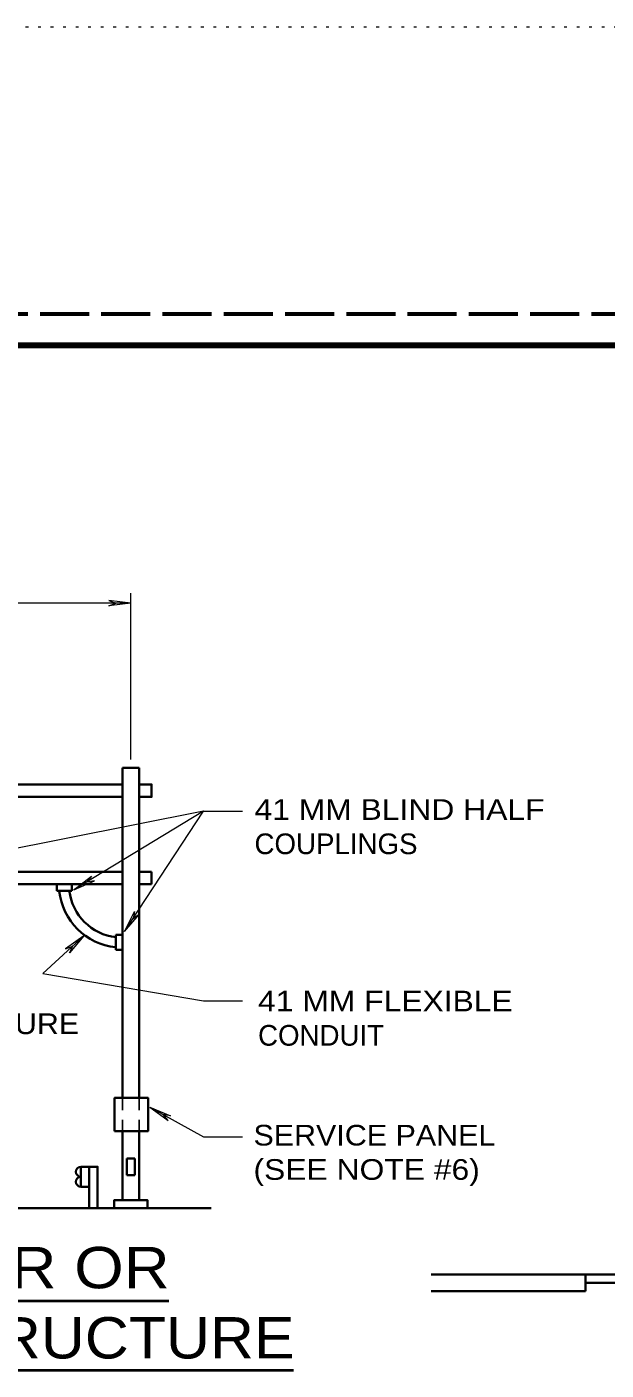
# Model space of a CAD drawing. Extents: x 312583 to 312854, y 144419 to 144597.
# Drawn here: x 312799.97 to 312821.24, y 144547.42 to 144596.78 of the extents above; entities that cross this region are included whole.
import ezdxf
from ezdxf.enums import TextEntityAlignment as Align

# ---------------------------------------------------------------- set-up
doc = ezdxf.new("R2010")
doc.units = 0
doc.header["$LTSCALE"] = 0.3
for name, pattern in [('DOTTED', [1.5, 0.3, -1.2]), ('LONG_DASHED', [7.5, 6, -1.5]), ('SHORT_DASHED', [2.7, 1.5, -1.2])]:
    doc.linetypes.add(name, pattern=pattern)
doc.layers.add('1', color=7, linetype='Continuous', lineweight=13)
doc.layers.add('63', color=7, linetype='DOTTED', lineweight=13)

msp = doc.modelspace()

# ---------------------------------------------------------------- linework, layer by layer
at = {"layer": '1', "linetype": 'LONG_DASHED', "lineweight": 60}
msp.add_line((312851.75, 144586.2246), (312583.526, 144586.2246), dxfattribs=at)
at = {"layer": '1', "lineweight": 158}
msp.add_line((312616.5, 144585.0846), (312849, 144585.0846), dxfattribs=at)
at = {"layer": '1'}
for p, q in [((312803.7798, 144575.6109), (312782.7042, 144575.6109)), ((312802.9748, 144575.7105), (312803.2278, 144575.6109)), ((312803.7798, 144575.6109), (312802.9748, 144575.7105)), ((312802.9748, 144575.5112), (312803.2278, 144575.6109)), ((312803.7798, 144575.6109), (312802.9748, 144575.5112)), ((312803.7798, 144569.8609), (312803.7798, 144575.9712)), ((312806.4478, 144567.9595), (312791.1528, 144564.9235)), ((312806.4478, 144567.9595), (312807.8892, 144567.9595)), ((312801.6945, 144565.0692), (312802.3385, 144565.5752)), ((312801.6945, 144565.0692), (312802.4458, 144565.3989)), ((312802.3385, 144565.5752), (312802.1698, 144565.3529)), ((312802.4458, 144565.3989), (312802.1698, 144565.3529)), ((312803.5575, 144563.5435), (312803.9178, 144564.2795)), ((312803.5575, 144563.5435), (312804.0865, 144564.1722)), ((312803.9178, 144564.2795), (312803.8642, 144564.0112)), ((312804.0865, 144564.1722), (312803.8642, 144564.0112)), ((312802.0548, 144563.3825), (312801.3878, 144562.9072)), ((312802.0548, 144563.3825), (312801.5258, 144562.7615)), ((312801.3878, 144562.9072), (312801.6485, 144563.0069)), ((312801.5258, 144562.7615), (312801.6485, 144563.0069)), ((312806.4478, 144560.9905), (312807.8892, 144560.9905)), ((312804.4852, 144557.0805), (312806.4478, 144555.9995)), ((312804.4852, 144557.0805), (312805.1522, 144556.5975)), ((312804.4852, 144557.0805), (312805.2442, 144556.7739)), ((312805.1522, 144556.5975), (312804.9758, 144556.8122)), ((312805.2442, 144556.7739), (312804.9758, 144556.8122)), ((312806.4478, 144555.9995), (312807.8892, 144555.9995))]:
    msp.add_line(p, q, dxfattribs=at)
at = {"layer": '1', "lineweight": 35}
for p, q in [((312804.0865, 144569.5542), (312803.4808, 144569.5542)), ((312803.4808, 144557.4255), (312803.4808, 144569.5542)), ((312804.0865, 144557.4255), (312804.0865, 144569.5542)), ((312803.4808, 144568.9485), (312791.8735, 144568.9485)), ((312803.4808, 144568.4885), (312791.8735, 144568.4885)), ((312803.4808, 144565.7362), (312791.8735, 144565.7362)), ((312804.0865, 144565.7362), (312804.5465, 144565.7362)), ((312804.5465, 144565.7362), (312804.5465, 144565.2839)), ((312803.4808, 144565.2839), (312791.8735, 144565.2839)), ((312801.0658, 144565.0385), (312801.0658, 144565.2839)), ((312801.6178, 144565.0385), (312801.6178, 144565.2839)), ((312804.0865, 144565.2839), (312804.5465, 144565.2839)), ((312801.6178, 144565.0385), (312801.0658, 144565.0385)), ((312803.2355, 144562.8689), (312803.2355, 144563.4209)), ((312803.2355, 144563.4209), (312803.4808, 144563.4209)), ((312803.2355, 144562.8689), (312803.4808, 144562.8689)), ((312803.4808, 144553.6689), (312803.4808, 144556.2065)), ((312804.0865, 144553.6689), (312804.0865, 144556.2065)), ((312801.9475, 144554.8955), (312801.9475, 144554.1595)), ((312802.2542, 144554.8955), (312802.2542, 144553.3699)), ((312803.6342, 144555.2022), (312803.9332, 144555.2022)), ((312803.6342, 144554.5889), (312803.6342, 144555.2022)), ((312803.9332, 144554.5889), (312803.9332, 144555.2022)), ((312803.6342, 144554.5889), (312803.9332, 144554.5889)), ((312802.2542, 144554.1595), (312801.9475, 144554.1595)), ((312798.2828, 144553.3699), (312806.7315, 144553.3699)), ((312820.4766, 144550.9337), (312814.811, 144550.9337)), ((312820.4766, 144550.9337), (312820.4766, 144550.3203)), ((312820.4766, 144550.3203), (312814.811, 144550.3203))]:
    msp.add_line(p, q, dxfattribs=at)
at = {"layer": '1', "linetype": 'SHORT_DASHED', "lineweight": 25}
for p, q in [((312803.4808, 144557.4255), (312803.4808, 144556.2065)), ((312804.0865, 144557.4255), (312804.0865, 144556.2065))]:
    msp.add_line(p, q, dxfattribs=at)
at = {"layer": '1', "lineweight": 40}
for p, q in [((312776.2125, 144549.9677), (312805.1771, 144549.9677)), ((312770.6431, 144547.4229), (312809.7605, 144547.4229))]:
    msp.add_line(p, q, dxfattribs=at)
at = {"layer": '1', "lineweight": 35}
for points in [[(312804.0865, 144568.9485), (312804.5465, 144568.9485), (312804.5465, 144568.4885), (312804.0865, 144568.4885)], [(312802.5608, 144553.3699), (312802.5608, 144554.8955), (312801.9475, 144554.8955)], [(312804.3932, 144553.3699), (312804.3932, 144553.6689), (312803.1742, 144553.6689), (312803.1742, 144553.3699)], [(312820.4766, 144550.9337), (312824.1413, 144550.9337), (312824.1413, 144550.627), (312820.4766, 144550.627)]]:
    msp.add_lwpolyline(points, dxfattribs=at)
at = {"layer": '1'}
for points in [[(312803.5575, 144563.5435), (312806.4478, 144567.9595), (312801.6945, 144565.0692)], [(312802.0548, 144563.3825), (312800.5522, 144561.9949), (312806.4478, 144560.9905)]]:
    msp.add_lwpolyline(points, dxfattribs=at)
at = {"layer": '1', "lineweight": 35}
msp.add_lwpolyline([(312803.1895, 144556.2065), (312803.1895, 144557.4255), (312804.4162, 144557.4255), (312804.4162, 144556.2065)], close=True, dxfattribs=at)
for centre, radius, start, end in [((312803.478, 144565.2802), 2.3335, 186.17349, 263.82647), ((312803.478, 144565.2802), 1.9669, 186.92092, 263.07914), ((312801.9507, 144554.711), 0.1833, 90, 270), ((312801.9507, 144554.3444), 0.1833, 90, 270)]:
    msp.add_arc(centre, radius, start, end, dxfattribs=at)
at = {"layer": '63'}
msp.add_line((312601.2, 144596.7846), (312853.5, 144596.7846), dxfattribs=at)

# ---------------------------------------------------------------- texts
at = {"layer": '1'}
for s, width, p in [('41 MM BLIND HALF', 1.15, (312808.3262, 144567.6442)), ('41 MM FLEXIBLE', 1.15, (312808.4565, 144560.6062)), ('LIGHTING FIXTURE', 1.1, (312791.5132, 144559.7705)), ('SERVICE PANEL', 1.1, (312808.2878, 144555.6765)), ('(SEE NOTE #6)', 1.15, (312808.2878, 144554.4165))]:
    msp.add_text(s, height=0.76, dxfattribs=dict(at, width=width)).set_placement(p)
for s, p in [('COUPLINGS', (312808.3262, 144566.3842)), ('CONDUIT', (312808.4565, 144559.3462))]:
    msp.add_text(s, height=0.76, dxfattribs=at).set_placement(p)
for s, width, p in [('TYPICAL CANTILEVER OR', 1.15, (312790.5979, 144550.4308)), ('HALF ROADWAY SPAN STRUCTURE', 1.1, (312790.2923, 144547.8506))]:
    msp.add_text(s, height=1.52, dxfattribs=dict(at, width=width)).set_placement(p, align=Align.CENTER)

doc.saveas('drawing.dxf')
